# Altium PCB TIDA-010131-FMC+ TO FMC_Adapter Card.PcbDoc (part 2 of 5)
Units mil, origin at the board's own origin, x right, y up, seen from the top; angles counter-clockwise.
Board outline 2874.02 x 2362.2 mil, 12 copper layers (L1_Top Layer, L2_GND, L3_GND, L4_Signal layer1, L5_GND, L6_Signal Layer2, L7_GND, L8_Signal Layer3, L9_GND, L10_Signal Layer4, L11_GND, L12_Bottom Layer), stack 65.6 mil thick; 64 components, 219 nets, 2252 pads, 791 vias.
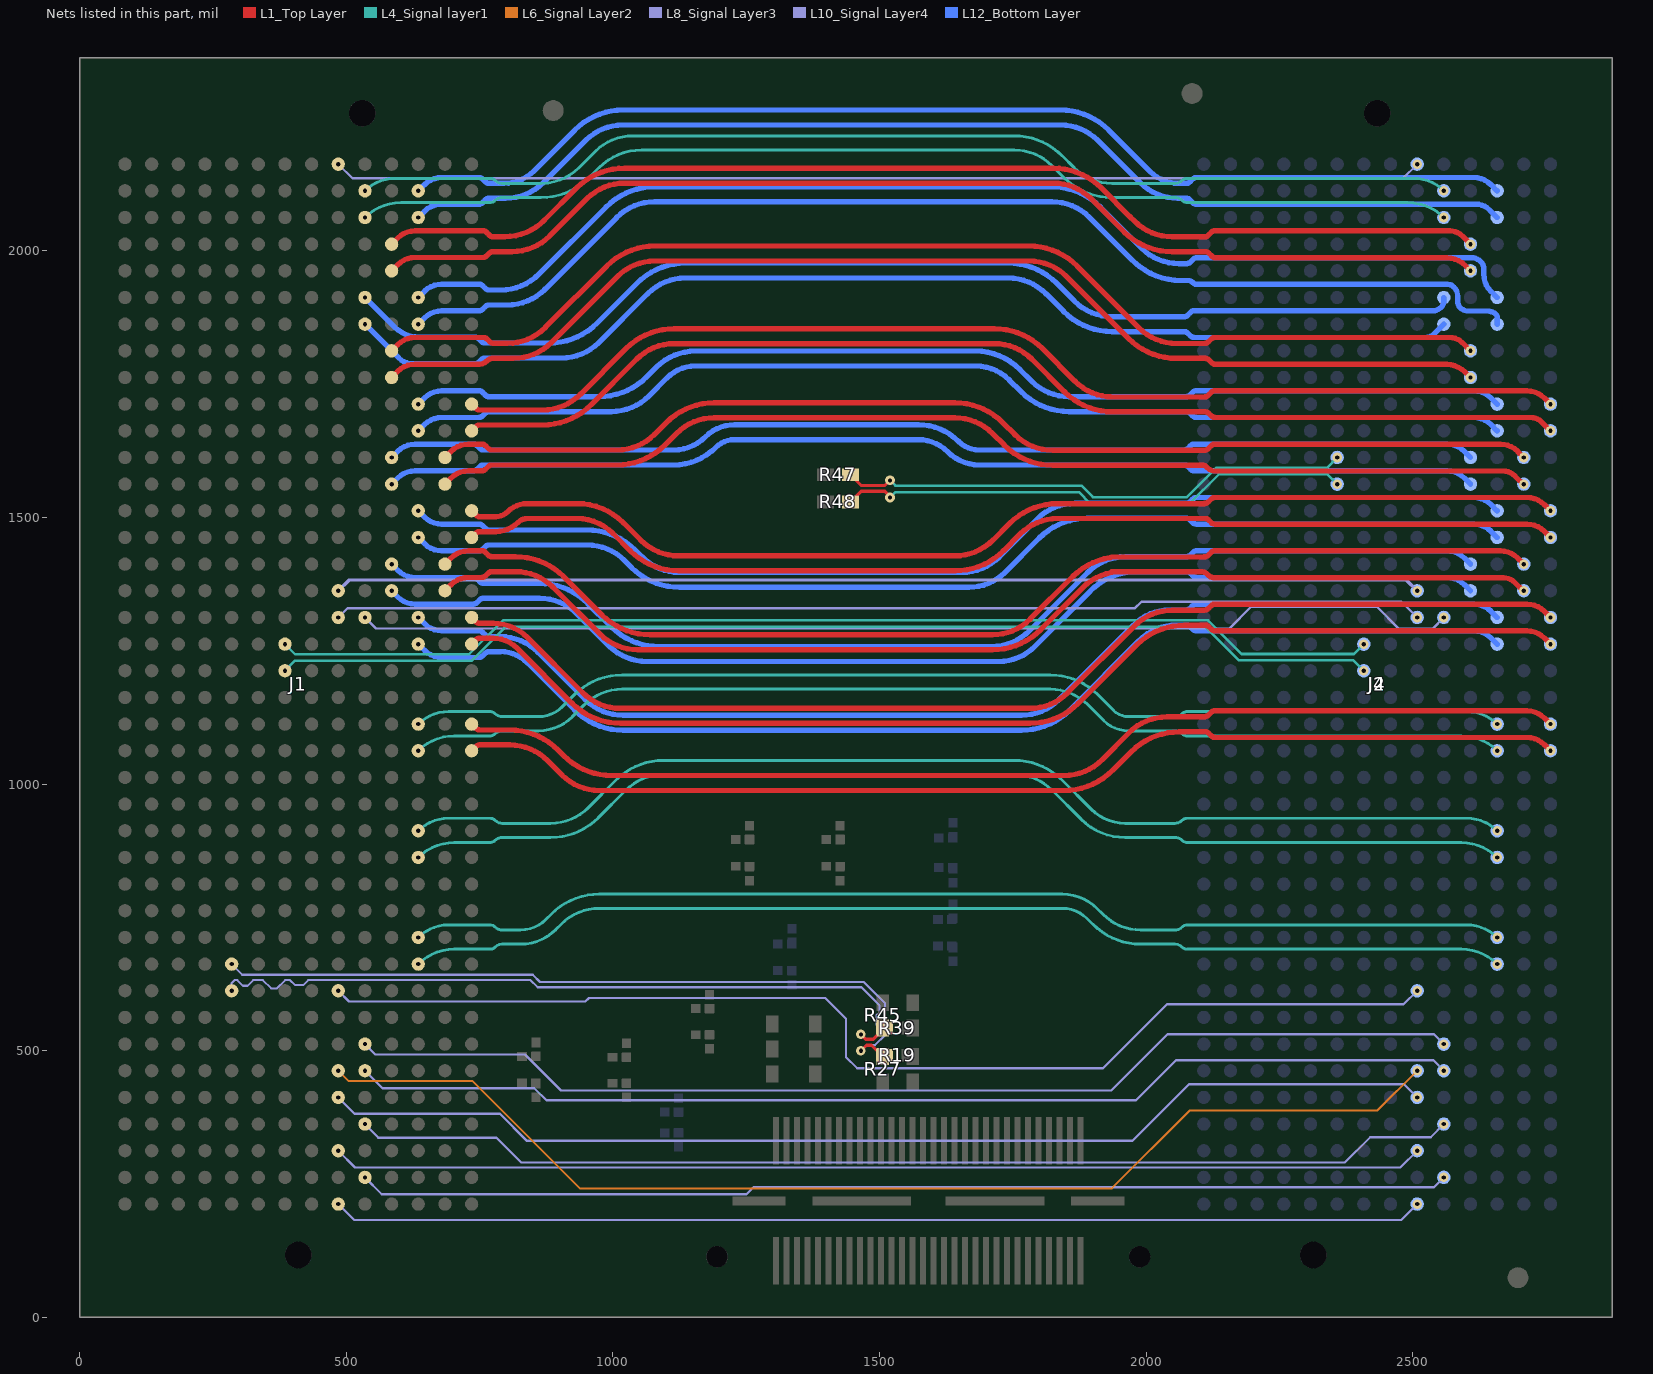
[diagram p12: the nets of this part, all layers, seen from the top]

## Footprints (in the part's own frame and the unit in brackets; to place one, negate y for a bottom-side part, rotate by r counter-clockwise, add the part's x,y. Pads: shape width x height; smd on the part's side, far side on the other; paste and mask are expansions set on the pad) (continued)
Samtec_ASP-184329-01 [mil] "Socket, 50 mil, 40x14, Gold, SMT"
  round 25 smd paste-25.2: A1(-975,225) A2(-925,225) A3(-875,225) A4(-825,225) A5(-775,225) A6(-725,225) A7(-675,225) A8(-625,225) A9(-575,225) A10(-525,225) A11(-475,225) A12(-425,225) A13(-375,225) A14(-325,225) A15(-275,225) A16(-225,225) A17(-175,225) A18(-125,225) A19(-75,225) A20(-25,225) A21(25,225) A22(75,225) A23(125,225) A24(175,225) A25(225,225) A26(275,225) A27(325,225) A28(375,225) A29(425,225) A30(475,225) A31(525,225) A32(575,225) A33(625,225) A34(675,225) A35(725,225) A36(775,225) A37(825,225) A38(875,225) A39(925,225) A40(975,225) B1(-975,175) B2(-925,175) B3(-875,175) B4(-825,175) B5(-775,175) B6(-725,175) B7(-675,175) B8(-625,175) B9(-575,175) B10(-525,175) B11(-475,175) B12(-425,175) B13(-375,175) B14(-325,175) B15(-275,175) B16(-225,175) B17(-175,175) B18(-125,175) B19(-75,175) B20(-25,175) B21(25,175) B22(75,175) B23(125,175) B24(175,175) B25(225,175) B26(275,175) B27(325,175) B28(375,175) B29(425,175) B30(475,175) B31(525,175) B32(575,175) B33(625,175) B34(675,175) B35(725,175) B36(775,175) B37(825,175) B38(875,175) B39(925,175) B40(975,175) C1(-975,125) C2(-925,125) C3(-875,125) C4(-825,125) C5(-775,125) C6(-725,125) C7(-675,125) C8(-625,125) C9(-575,125) C10(-525,125) C11(-475,125) C12(-425,125) C13(-375,125) C14(-325,125) C15(-275,125) C16(-225,125) C17(-175,125) C18(-125,125) C19(-75,125) C20(-25,125) C21(25,125) C22(75,125) C23(125,125) C24(175,125) C25(225,125) C26(275,125) C27(325,125) C28(375,125) C29(425,125) C30(475,125) C31(525,125) C32(575,125) C33(625,125) C34(675,125) C35(725,125) C36(775,125) C37(825,125) C38(875,125) C39(925,125) C40(975,125) D1(-975,75) D2(-925,75) D3(-875,75) D4(-825,75) D5(-775,75) D6(-725,75) D7(-675,75) D8(-625,75) D9(-575,75) D10(-525,75) D11(-475,75) D12(-425,75) D13(-375,75) D14(-325,75) D15(-275,75) D16(-225,75) D17(-175,75) D18(-125,75) D19(-75,75) D20(-25,75) D21(25,75) D22(75,75) D23(125,75) D24(175,75) D25(225,75) D26(275,75) D27(325,75) D28(375,75) D29(425,75) D30(475,75) D31(525,75) D32(575,75) D33(625,75) D34(675,75) D35(725,75) D36(775,75) D37(825,75) D38(875,75) D39(925,75) D40(975,75) E1(-975,25) E2(-925,25) E3(-875,25) E4(-825,25) E5(-775,25) E6(-725,25) E7(-675,25) E8(-625,25) E9(-575,25) E10(-525,25) E11(-475,25) E12(-425,25) E13(-375,25) E14(-325,25) E15(-275,25) E16(-225,25) E17(-175,25) E18(-125,25) E19(-75,25) E20(-25,25) E21(25,25) E22(75,25) E23(125,25) E24(175,25) E25(225,25) E26(275,25) E27(325,25) E28(375,25) E29(425,25) E30(475,25) E31(525,25) E32(575,25) E33(625,25) E34(675,25) E35(725,25) E36(775,25) E37(825,25) E38(875,25) E39(925,25) E40(975,25) F1(-975,-25) F2(-925,-25) F3(-875,-25) F4(-825,-25) F5(-775,-25) F6(-725,-25) F7(-675,-25) F8(-625,-25) F9(-575,-25) F10(-525,-25) F11(-475,-25) F12(-425,-25) F13(-375,-25) F14(-325,-25) F15(-275,-25) F16(-225,-25) F17(-175,-25) F18(-125,-25) F19(-75,-25) F20(-25,-25) F21(25,-25) F22(75,-25) F23(125,-25) F24(175,-25) F25(225,-25) F26(275,-25) F27(325,-25) F28(375,-25) F29(425,-25) F30(475,-25) F31(525,-25) F32(575,-25) F33(625,-25) F34(675,-25) F35(725,-25) F36(775,-25) F37(825,-25) F38(875,-25) F39(925,-25) F40(975,-25) G1(-975,-75) G2(-925,-75) G3(-875,-75) G4(-825,-75) G5(-775,-75) G6(-725,-75) G7(-675,-75) G8(-625,-75) G9(-575,-75) G10(-525,-75) G11(-475,-75) G12(-425,-75) G13(-375,-75) G14(-325,-75) G15(-275,-75) G16(-225,-75) G17(-175,-75) G18(-125,-75) G19(-75,-75) G20(-25,-75) G21(25,-75) G22(75,-75) G23(125,-75) G24(175,-75) G25(225,-75) G26(275,-75) G27(325,-75) G28(375,-75) G29(425,-75) G30(475,-75) G31(525,-75) G32(575,-75) G33(625,-75) G34(675,-75) G35(725,-75) G36(775,-75) G37(825,-75) G38(875,-75) G39(925,-75) G40(975,-75) H1(-975,-125) H2(-925,-125) H3(-875,-125) H4(-825,-125) H5(-775,-125) H6(-725,-125) H7(-675,-125) H8(-625,-125) H9(-575,-125) H10(-525,-125) H11(-475,-125) H12(-425,-125) H13(-375,-125) H14(-325,-125) H15(-275,-125) H16(-225,-125) H17(-175,-125) H18(-125,-125) H19(-75,-125) H20(-25,-125) H21(25,-125) H22(75,-125) H23(125,-125) H24(175,-125) H25(225,-125) H26(275,-125) H27(325,-125) H28(375,-125) H29(425,-125) H30(475,-125) H31(525,-125) H32(575,-125) H33(625,-125) H34(675,-125) H35(725,-125) H36(775,-125) H37(825,-125) H38(875,-125) H39(925,-125) H40(975,-125) J1(-975,-175) J2(-925,-175) J3(-875,-175) J4(-825,-175) J5(-775,-175) J6(-725,-175) J7(-675,-175) J8(-625,-175) J9(-575,-175) J10(-525,-175) J11(-475,-175) J12(-425,-175) J13(-375,-175) J14(-325,-175) J15(-275,-175) J16(-225,-175) J17(-175,-175) J18(-125,-175) J19(-75,-175) J20(-25,-175) J21(25,-175) J22(75,-175) J23(125,-175) J24(175,-175) J25(225,-175) J26(275,-175) J27(325,-175) J28(375,-175) J29(425,-175) J30(475,-175) J31(525,-175) J32(575,-175) J33(625,-175) J34(675,-175) J35(725,-175) J36(775,-175) J37(825,-175) J38(875,-175) J39(925,-175) J40(975,-175) K1(-975,-225) K2(-925,-225) K3(-875,-225) K4(-825,-225) K5(-775,-225) K6(-725,-225) K7(-675,-225) K8(-625,-225) K9(-575,-225) K10(-525,-225) K11(-475,-225) K12(-425,-225) K13(-375,-225) K14(-325,-225) K15(-275,-225) K16(-225,-225) K17(-175,-225) K18(-125,-225) K19(-75,-225) K20(-25,-225) K21(25,-225) K22(75,-225) K23(125,-225) K24(175,-225) K25(225,-225) K26(275,-225) K27(325,-225) K28(375,-225) K29(425,-225) K30(475,-225) K31(525,-225) K32(575,-225) K33(625,-225) K34(675,-225) K35(725,-225) K36(775,-225) K37(825,-225) K38(875,-225) K39(925,-225) K40(975,-225) L1(-975,-275) L2(-925,-275) L3(-875,-275) L4(-825,-275) L5(-775,-275) L6(-725,-275) L7(-675,-275) L8(-625,-275) L9(-575,-275) L10(-525,-275) L11(-475,-275) L12(-425,-275) L13(-375,-275) L14(-325,-275) L15(-275,-275) L16(-225,-275) L17(-175,-275) L18(-125,-275) L19(-75,-275) L20(-25,-275) L21(25,-275) L22(75,-275) L23(125,-275) L24(175,-275) L25(225,-275) L26(275,-275) L27(325,-275) L28(375,-275) L29(425,-275) L30(475,-275) L31(525,-275) L32(575,-275) L33(625,-275) L34(675,-275) L35(725,-275) L36(775,-275) L37(825,-275) L38(875,-275) L39(925,-275) L40(975,-275) M1(-975,-325) M2(-925,-325) M3(-875,-325) M4(-825,-325) M5(-775,-325) M6(-725,-325) M7(-675,-325) M8(-625,-325) M9(-575,-325) M10(-525,-325) M11(-475,-325) M12(-425,-325) M13(-375,-325) M14(-325,-325) M15(-275,-325) M16(-225,-325) M17(-175,-325) M18(-125,-325) M19(-75,-325) M20(-25,-325) M21(25,-325) M22(75,-325) M23(125,-325) M24(175,-325) M25(225,-325) M26(275,-325) M27(325,-325) M28(375,-325) M29(425,-325) M30(475,-325) M31(525,-325) M32(575,-325) M33(625,-325) M34(675,-325) M35(725,-325) M36(775,-325) M37(825,-325) M38(875,-325) M39(925,-325) M40(975,-325) Y1(-975,325) Y2(-925,325) Y3(-875,325) Y4(-825,325) Y5(-775,325) Y6(-725,325) Y7(-675,325) Y8(-625,325) Y9(-575,325) Y10(-525,325) Y11(-475,325) Y12(-425,325) Y13(-375,325) Y14(-325,325) Y15(-275,325) Y16(-225,325) Y17(-175,325) Y18(-125,325) Y19(-75,325) Y20(-25,325) Y21(25,325) Y22(75,325) Y23(125,325) Y24(175,325) Y25(225,325) Y26(275,325) Y27(325,325) Y28(375,325) Y29(425,325) Y30(475,325) Y31(525,325) Y32(575,325) Y33(625,325) Y34(675,325) Y35(725,325) Y36(775,325) Y37(825,325) Y38(875,325) Y39(925,325) Y40(975,325) Z1(-975,275) Z2(-925,275) Z3(-875,275) Z4(-825,275) Z5(-775,275) Z6(-725,275) Z7(-675,275) Z8(-625,275) Z9(-575,275) Z10(-525,275) Z11(-475,275) Z12(-425,275) Z13(-375,275) Z14(-325,275) Z15(-275,275) Z16(-225,275) Z17(-175,275) Z18(-125,275) Z19(-75,275) Z20(-25,275) Z21(25,275) Z22(75,275) Z23(125,275) Z24(175,275) Z25(225,275) Z26(275,275) Z27(325,275) Z28(375,275) Z29(425,275) Z30(475,275) Z31(525,275) Z32(575,275) Z33(625,275) Z34(675,275) Z35(725,275) Z36(775,275) Z37(825,275) Z38(875,275) Z39(925,275) Z40(975,275)
  round 50 hole 50 unplated mask+5: ""(-1070.5,120) ""(1070.5,0)
  round 35 on Top Paste: ""(-975,325) ""(-975,-275) ""(-975,-225) ""(-975,-175) ""(-975,-125) ""(-975,-75) ""(-975,-25) ""(-975,25) ""(-975,75) ""(-975,125) ""(-975,175) ""(-975,225) ""(-975,275) ""(-975,-325) ""(-925,325) ""(-925,-175) ""(-925,-75) ""(-925,75) ""(-925,175) ""(-925,-275) ""(-925,-225) ""(-925,-125) ""(-925,-25) ""(-925,25) ""(-925,125) ""(-925,225) ""(-925,275) ""(-925,-325) ""(-875,325) ""(-875,-275) ""(-875,-225) ""(-875,-175) ""(-875,-125) ""(-875,-75) ""(-875,-25) ""(-875,25) ""(-875,75) ""(-875,125) ""(-875,175) ""(-875,225) ""(-875,275) ""(-875,-325) ""(-825,325) ""(-825,-275) ""(-825,-175) ""(-825,-125) ""(-825,-75) ""(-825,-25) ""(-825,25) ""(-825,75) ""(-825,125) ""(-825,175) ""(-825,225) ""(-825,275) ""(-825,-325) ""(-825,-225) ""(-775,325) ""(-775,-275) ""(-775,-225) ""(-775,-125) ""(-775,-75) ""(-775,-25) ""(-775,25) ""(-775,125) ""(-775,175) ""(-775,225) ""(-775,275) ""(-775,-325) ""(-775,-175) ""(-775,75) ""(-725,-275) ""(-725,275) ""(-725,325) ""(-725,-225) ""(-725,-175) ""(-725,-125) ""(-725,-75) ""(-725,-25) ""(-725,25) ""(-725,75) ""(-725,125) ""(-725,175) ""(-725,225) ""(-725,-325) ""(-675,325) ""(-675,-275) ""(-675,-225) ""(-675,-175) ""(-675,-125) ""(-675,-75) ""(-675,-25) ""(-675,25) ""(-675,75) ""(-675,125) ""(-675,175) ""(-675,225) ""(-675,275) ""(-675,-325) ""(-625,325) ""(-625,-225) ""(-625,-175) ""(-625,-125) ""(-625,-75) ""(-625,25) ""(-625,75) ""(-625,125) ""(-625,175) ""(-625,275) ""(-625,-325) ""(-625,-275) ""(-625,-25) ""(-625,225) ""(-575,325) ""(-575,-275) ""(-575,-175) ""(-575,-75) ""(-575,-25) ""(-575,75) ""(-575,125) ""(-575,175) ""(-575,225) ""(-575,-325) ""(-575,-225) ""(-575,-125) ""(-575,25) ""(-575,275) ""(-525,325) ""(-525,-275) ""(-525,-225) ""(-525,-125) ""(-525,-75) ""(-525,-25) ""(-525,25) ""(-525,75) ""(-525,125) ""(-525,175) ""(-525,225) ""(-525,275) ""(-525,-325) ""(-525,-175) ""(-475,275) ""(-475,-25) ""(-475,25) ""(-475,-275) ""(-475,175) ""(-475,225) ""(-475,325) ""(-475,-125) ""(-475,-75) ""(-475,75) ""(-475,125) ""(-475,-325) ""(-475,-225) ""(-475,-175) ""(-425,175) ""(-425,225) ""(-425,275) ""(-425,325) ""(-425,-125) ""(-425,-75) ""(-425,-25) ""(-425,25) ""(-425,75) ""(-425,125) ""(-425,-325) ""(-425,-275) ""(-425,-225) ""(-425,-175) ""(-375,175) ""(-375,275) ""(-375,325) ""(-375,-125) ""(-375,-75) ""(-375,25) ""(-375,75) ""(-375,125) ""(-375,-325) ""(-375,-275) ""(-375,-225) ""(-375,-175) ""(-375,225) ""(-375,-25) ""(-325,175) ""(-325,225) ""(-325,325) ""(-325,-125) ""(-325,-75) ""(-325,-25) ""(-325,75) ""(-325,125) ""(-325,-325) ""(-325,-275) ""(-325,-225) ""(-325,-175) ""(-325,275) ""(-325,25) ""(-275,-175) ""(-275,175) ""(-275,225) ""(-275,275) ""(-275,325) ""(-275,-125) ""(-275,-75) ""(-275,-25) ""(-275,25) ""(-275,75) ""(-275,125) ""(-275,-325) ""(-275,-275) ""(-275,-225) ""(-225,275) ""(-225,225) ""(-225,-25) ""(-225,25) ""(-225,-225) ""(-225,-125) ""(-225,-275) ""(-225,325) ""(-225,125) ""(-225,175) ""(-225,-75) ""(-225,75) ""(-225,-175) ""(-225,-325) ""(-175,275) ""(-175,325) ""(-175,125) ""(-175,225) ""(-175,-75) ""(-175,-25) ""(-175,75) ""(-175,-175) ""(-175,-125) ""(-175,-325) ""(-175,-275) ""(-175,175) ""(-175,25) ""(-175,-225) ""(-125,275) ""(-125,125) ""(-125,175) ""(-125,-25) ""(-125,25) ""(-125,-75) ""(-125,-125) ""(-125,-225) ""(-125,-325) ""(-125,-275) ""(-125,325) ""(-125,225) ""(-125,75) ""(-125,-175) ""(-75,325) ""(-75,225) ""(-75,125) ""(-75,175) ""(-75,75) ""(-75,-25) ""(-75,25) ""(-75,-75) ""(-75,-175) ""(-75,-125) ""(-75,-225) ""(-75,-325) ""(-75,-275) ""(-75,275) ""(-25,175) ""(-25,75) ""(-25,-175) ""(-25,325) ""(-25,275) ""(-25,225) ""(-25,125) ""(-25,25) ""(-25,-25) ""(-25,-75) ""(-25,-125) ""(-25,-225) ""(-25,-275) ""(-25,-325) ""(25,325) ""(25,275) ""(25,225) ""(25,175) ""(25,125) ""(25,75) ""(25,25) ""(25,-25) ""(25,-75) ""(25,-125) ""(25,-175) ""(25,-225) ""(25,-275) ""(25,-325) ""(75,275) ""(75,325) ""(75,225) ""(75,125) ""(75,175) ""(75,75) ""(75,-25) ""(75,25) ""(75,-75) ""(75,-175) ""(75,-125) ""(75,-325) ""(75,-275) ""(75,-225) ""(125,275) ""(125,325) ""(125,225) ""(125,125) ""(125,175) ""(125,-25) ""(125,25) ""(125,-75) ""(125,-125) ""(125,-225) ""(125,-325) ""(125,-275) ""(125,75) ""(125,-175) ""(175,275) ""(175,325) ""(175,125) ""(175,175) ""(175,225) ""(175,-75) ""(175,-25) ""(175,25) ""(175,75) ""(175,-225) ""(175,-175) ""(175,-125) ""(175,-325) ""(175,-275) ""(225,325) ""(225,175) ""(225,-75) ""(225,75) ""(225,-175) ""(225,275) ""(225,125) ""(225,225) ""(225,-25) ""(225,25) ""(225,-225) ""(225,-125) ""(225,-325) ""(225,-275) ""(275,175) ""(275,225) ""(275,275) ""(275,325) ""(275,-125) ""(275,-75) ""(275,-25) ""(275,25) ""(275,75) ""(275,125) ""(275,-325) ""(275,-275) ""(275,-225) ""(275,-175) ""(325,175) ""(325,225) ""(325,275) ""(325,325) ""(325,-125) ""(325,-75) ""(325,-25) ""(325,25) ""(325,75) ""(325,125) ""(325,-325) ""(325,-275) ""(325,-225) ""(325,-175) ""(375,175) ""(375,225) ""(375,275) ""(375,325) ""(375,-125) ""(375,-75) ""(375,-25) ""(375,25) ""(375,75) ""(375,125) ""(375,-325) ""(375,-275) ""(375,-225) ""(375,-175) ""(425,275) ""(425,-275) ""(425,175) ""(425,225) ""(425,325) ""(425,-125) ""(425,-75) ""(425,-25) ""(425,25) ""(425,75) ""(425,125) ""(425,-325) ""(425,-225) ""(425,-175) ""(475,175) ""(475,225) ""(475,275) ""(475,325) ""(475,-125) ""(475,-75) ""(475,-25) ""(475,25) ""(475,75) ""(475,125) ""(475,-325) ""(475,-275) ""(475,-225) ""(475,-175) ""(525,325) ""(525,-275) ""(525,-225) ""(525,-175) ""(525,-125) ""(525,-75) ""(525,25) ""(525,75) ""(525,125) ""(525,175) ""(525,275) ""(525,-325) ""(525,-25) ""(525,225) ""(575,325) ""(575,-275) ""(575,-225) ""(575,-175) ""(575,-125) ""(575,-75) ""(575,-25) ""(575,75) ""(575,125) ""(575,175) ""(575,225) ""(575,-325) ""(575,25) ""(575,275) ""(625,-175) ""(625,325) ""(625,-275) ""(625,-225) ""(625,-125) ""(625,-75) ""(625,-25) ""(625,25) ""(625,75) ""(625,125) ""(625,175) ""(625,225) ""(625,275) ""(625,-325) ""(675,-275) ""(675,-125) ""(675,-25) ""(675,25) ""(675,275) ""(675,325) ""(675,-225) ""(675,-175) ""(675,-75) ""(675,75) ""(675,125) ""(675,175) ""(675,225) ""(675,-325) ""(725,325) ""(725,-275) ""(725,-225) ""(725,-175) ""(725,-125) ""(725,-75) ""(725,-25) ""(725,25) ""(725,75) ""(725,125) ""(725,175) ""(725,225) ""(725,275) ""(725,-325) ""(775,325) ""(775,-275) ""(775,-225) ""(775,-175) ""(775,-125) ""(775,-75) ""(775,-25) ""(775,25) ""(775,75) ""(775,125) ""(775,175) ""(775,275) ""(775,-325) ""(775,225) ""(825,325) ""(825,-275) ""(825,-225) ""(825,-175) ""(825,-125) ""(825,-75) ""(825,-25) ""(825,25) ""(825,75) ""(825,125) ""(825,175) ""(825,225) ""(825,-325) ""(825,275) ""(875,-175) ""(875,75) ""(875,175) ""(875,325) ""(875,-275) ""(875,-225) ""(875,-125) ""(875,-75) ""(875,-25) ""(875,25) ""(875,125) ""(875,225) ""(875,275) ""(875,-325) ""(925,325) ""(925,-275) ""(925,-225) ""(925,-175) ""(925,-125) ""(925,-75) ""(925,-25) ""(925,25) ""(925,75) ""(925,125) ""(925,175) ""(925,225) ""(925,275) ""(925,-325) ""(975,325) ""(975,-275) ""(975,-175) ""(975,-125) ""(975,-75) ""(975,-25) ""(975,75) ""(975,125) ""(975,175) ""(975,225) ""(975,275) ""(975,-325) ""(975,-225) ""(975,25)
  silkscreen extent -1128,-362 1135,374, body extent -1131,-362 1131,362, height 267
Samtec_QSH-030-01-X-D-A [mm] "Receptacle, 0.5 mm, 30x2, TH"
  rect 2.27x0.279 smd: 1(-2.865,7.25) 2(2.865,7.25) 3(-2.865,6.75) 4(2.865,6.75) 5(-2.865,6.25) 6(2.865,6.25) 7(-2.865,5.75) 8(2.865,5.75) 9(-2.865,5.25) 10(2.865,5.25) 11(-2.865,4.75) 12(2.865,4.75) 13(-2.865,4.25) 14(2.865,4.25) 15(-2.865,3.75) 16(2.865,3.75) 17(-2.865,3.25) 18(2.865,3.25) 19(-2.865,2.75) 20(2.865,2.75) 21(-2.865,2.25) 22(2.865,2.25) 23(-2.865,1.75) 24(2.865,1.75) 25(-2.865,1.25) 26(2.865,1.25) 27(-2.865,0.75) 28(2.865,0.75) 29(-2.865,0.25) 30(2.865,0.25) 31(-2.865,-0.25) 32(2.865,-0.25) 33(-2.865,-0.75) 34(2.865,-0.75) 35(-2.865,-1.25) 36(2.865,-1.25) 37(-2.865,-1.75) 38(2.865,-1.75) 39(-2.865,-2.25) 40(2.865,-2.25) 41(-2.865,-2.75) 42(2.865,-2.75) 43(-2.865,-3.25) 44(2.865,-3.25) 45(-2.865,-3.75) 46(2.865,-3.75) 47(-2.865,-4.25) 48(2.865,-4.25) 49(-2.865,-4.75) 50(2.865,-4.75) 51(-2.865,-5.25) 52(2.865,-5.25) 53(-2.865,-5.75) 54(2.865,-5.75) 55(-2.865,-6.25) 56(2.865,-6.25) 57(-2.865,-6.75) 58(2.865,-6.75) 59(-2.865,-7.25) 60(2.865,-7.25)
  round 1.02 hole 1.02 unplated mask+0.127: MH1(2.67,10.065) MH2(2.67,-10.065)
  rect 0.43x2.54 smd: MP1(0,8.065) MP4(0,-8.065)
  rect 0.43x4.7 smd: MP2(0,3.175) MP3(0,-3.175)
  silkscreen extent -3.9,-10.66 3.62,10.66, body extent -3.75,-10.64 3.75,10.67, height 3.25
WEEE_Minimum [mil] "WEEElie bin"
  silkscreen extent -95,-172 99,104

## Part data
FID1 FID2 FID3: "Fiducial mark.  There is nothing to buy or mount.", Manufacturer=N/A
J1: "Socket, 50 mil, 40x14, Gold, SMT", Color=Black, Manufacturer=Samtec, Supplier Part Number 1=SAM9172-ND
J2: "Connector, 1.27mm, 40x10, Black, SMT", Color=Black, Manufacturer=Samtec, Supplier Part Number 1=2433503
J3: "Receptacle, 0.5 mm, 30x2, Gold, TH", Color=Black, Manufacturer=Samtec, Supplier Part Number 1=SAM8180-ND
J4: "14 ROW .050 PITCH TERMINAL ARRAY ASM.", Manufacturer=SAMTEC
LBL1: library part THT-14-423-10, "Thermal Transfer Printable Labels, 0.650\" W x 0.200\" H - 10,000 per roll", Alternate Manufacturer=-, Manufacturer=Brady, Supplier Part Number 1=2065596
Logo1: library part ESD_Susceptible, "ESD Susceptible Symbol"
Logo2: library part Pb-Free
Logo3: library part FCC_disclaimer, "FCC_disclaimer"
Logo4: library part CMP-0074769-1
R1 R2 R3 R4 R5 R6 R9 R10 R11 R12 R13 R14 R15 R16 R17 R18 R20 R21 R22 R23 R24 R26 R28 R29 R30 R31 R32 R33 R34 R35 R36 R37 R41 R42 R43 R44: "RES, 0, 5%, 0.05 W, AEC-Q200 Grade 0, 0201", Manufacturer=Panasonic, Power_W=0.05, Supplier Part Number 1=P15979CT-ND, TempCo=ppm/C, Tolerance_%=5, Value1=5%, Value2=0.05W, Value_Code=0000, ValueDisplayed=0
R7 R8 R19 R25 R27 R38 R39 R40 R45 R46 R47 R48: "RES, 0, 5%, 0.063 W, 0402", Manufacturer=Vishay-Dale, Power_W=0.063, Supplier Part Number 1=541-0.0JCT-ND, TempCo="200 ppm/C", Tolerance_%=5, Value1=5%, Value2=0.063W, Value_Code=0000, ValueDisplayed=0
ZZ1: library part AssemblyNoteLabel, Alternate Manufacturer=-
ZZ2 ZZ3 ZZ4: library part AssemblyNote, Alternate Manufacturer=-

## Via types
v1: diameter 18, hole 8, L1_Top Layer to L12_Bottom Layer, 791 vias

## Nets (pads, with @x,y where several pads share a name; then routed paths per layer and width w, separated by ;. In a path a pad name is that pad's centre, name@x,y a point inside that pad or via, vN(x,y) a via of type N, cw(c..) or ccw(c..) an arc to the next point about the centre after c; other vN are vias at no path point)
ADC_ALT_SYNC_N: J1.H32 R39.1 R45.2 | length 1439.1
  L1_Top Layer w6: v1(1465,530.62) 1474.19,521.43 1488.19,521.43 R39.1@1509.38,542.62
  L8_Signal Layer3 w4: v1(285,612.5) 285,627 290.5,632.5 295.5,632.5 306,622 315,622 325.5,632.5 343.5,632.5 359,617 370,617 385.5,632.5 394.5,632.5 404,623 419,623 428.5,632.5 845.5,632.5 859,619 1466,619 1500,585 1500,572 1494,566 1494,549 1500,543 1500,533.32 1487,520.32 1475.3,520.32 v1(1465,530.62)
ADC_ALT_SYNC_P: J1.H31 R19.1 R27.1 | length 1426.5
  L1_Top Layer w6: v1(1465,500.02) 1475.41,510.43 1484.81,510.43 R27.1@1506,489.24
  L8_Signal Layer3 w4: v1(285,662.5) 305,642.5 849.64,642.5 863.14,629 1470.14,629 1510,589.14 1510,529.18 1491.14,510.32 1475.3,510.32 v1(1465,500.02)
ADC_DA0_N: J1.C7 J2.C7 J4.C7 | length 2154.5
  L12_Bottom Layer w10: v1(535,1862.5) 598.54,1798.96 ccw(c625,1825.42) 625,1788 741,1788 ccw(c741,1797.99) 748.07,1790.93 753.21,1796.07 cw(c760.28,1789.01) 760.28,1799 903.18,1799 ccw(c903.18,1899) 973.89,1828.29 1065.31,1919.71 cw(c1136.02,1849) 1136.02,1949 1740.98,1949 cw(c1740.98,1849) 1811.69,1919.71 1845.41,1885.99 ccw(c1935.92,1976.5) 1935.92,1848.5 2070.72,1848.5 cw(c2070.72,1838.51) 2077.79,1845.57 2082.93,1840.43 ccw(c2090,1847.49) 2090,1837.5 2524.64,1837.5 ccw(c2524.64,1857.67) 2538.91,1843.41 J2.C7@2558,1862.5
ADC_DA0_P: J1.C6 J2.C6 J4.C6 | length 2154.9
  L12_Bottom Layer w10: v1(535,1912.5) 590.05,1857.45 ccw(c637,1904.39) 637,1838 741,1838 cw(c741,1828.01) 748.07,1835.07 753.21,1829.93 ccw(c760.28,1836.99) 760.28,1827 879.98,1827 ccw(c879.98,1955) 970.49,1864.49 1045.51,1939.51 cw(c1136.02,1849) 1136.02,1977 1695.58,1977 ; 1698.6,1977 1740.98,1977 cw(c1740.98,1849) 1831.49,1939.51 1865.21,1905.79 ccw(c1935.92,1976.5) 1935.92,1876.5 2070.72,1876.5 ccw(c2070.72,1886.49) 2077.79,1879.43 2082.93,1884.57 cw(c2090,1877.51) 2090,1887.5 2537.31,1887.5 ccw(c2537.31,1909.69) 2553,1894 ccw(c2540.93,1906.07) 2558,1906.07 J2.C6@2558,1912.5
ADC_DA1_N: J1.A3 J2.A3 J4.A3 | length 2144.2
  L12_Bottom Layer w10: v1(635,2062.5) 646.53,2074.03 cw(c679.05,2041.51) 679.05,2087.5 748.5,2087.5 ccw(c748.5,2097.49) 755.57,2090.43 760.71,2095.57 cw(c767.78,2088.51) 767.78,2098.5 798.68,2098.5 ccw(c798.68,2198.5) 869.39,2127.79 948.31,2206.71 cw(c1019.02,2136) 1019.02,2236 1838.98,2236 cw(c1838.98,2136) 1909.69,2206.71 1988.61,2127.79 ccw(c2059.32,2198.5) 2059.32,2098.5 2074.91,2098.5 cw(c2074.91,2088.51) 2081.98,2095.57 2087.12,2090.43 ccw(c2094.19,2097.49) 2094.19,2087.5 2617.37,2087.5 cw(c2617.37,2049.77) 2644.05,2076.45 ; 2644.05,2076.45 J2.A3@2658,2062.5
ADC_DA1_P: J1.A2 J2.A2 J4.A2 | length 2143.3
  L12_Bottom Layer w10: v1(635,2112.5) 646.53,2124.03 cw(c679.05,2091.51) 679.05,2137.5 748.5,2137.5 cw(c748.5,2127.51) 755.57,2134.57 760.71,2129.43 ccw(c767.78,2136.49) 767.78,2126.5 795.27,2126.5 ccw(c795.27,2206.73) 852,2150 928.51,2226.51 cw(c1019.02,2136) 1019.02,2264 1838.98,2264 cw(c1838.98,2136) 1929.49,2226.51 2007.23,2148.77 ccw(c2061,2202.55) 2061,2126.5 2074.91,2126.5 ccw(c2074.91,2136.49) 2081.98,2129.43 2087.12,2134.57 cw(c2094.19,2127.51) 2094.19,2137.5 2613.95,2137.5 cw(c2613.95,2091.51) 2646.47,2124.03 J2.A2@2658,2112.5
ADC_DA2_N: J1.A7 J2.A7 J4.A7 | length 2211.5
  L12_Bottom Layer w10: v1(635,1862.5) 646.53,1874.03 cw(c679.05,1841.51) 679.05,1887.5 748.5,1887.5 ccw(c748.5,1897.49) 755.57,1890.43 760.71,1895.57 cw(c767.78,1888.51) 767.78,1898.5 801.68,1898.5 ccw(c801.68,1998.5) 872.39,1927.79 1007.31,2062.71 cw(c1078.02,1992) 1078.02,2092 1822.98,2092 cw(c1822.98,1992) 1893.69,2062.71 1974.57,1981.84 ccw(c2065.07,2072.35) 1988.2,1970 ccw(c2065.07,2072.35) 2030.28,1949.17 ccw(c2065.07,2072.35) 2065.07,1944.35 2080.51,1944.35 cw(c2075.52,1927.52) 2087.77,1940.09 cw(c2075.52,1927.52) 2087.93,1939.93 ccw(c2095,1946.99) 2095,1937 2564.93,1937 cw(c2564.93,1919.93) 2577,1932 cw(c2560.1,1915.1) 2584,1915.1 2584,1904.66 ccw(c2600.07,1904.66) 2588.71,1893.29 ccw(c2603.9,1908.49) 2603.9,1887 2640.31,1887 cw(c2640.31,1864.81) 2656,1880.5 cw(c2651.17,1875.67) 2658,1875.67 J2.A7@2658,1862.5
ADC_DA2_P: J1.A6 J2.A6 J4.A6 | length 2207.3
  L12_Bottom Layer w10: v1(635,1912.5) 646.53,1924.03 cw(c679.05,1891.51) 679.05,1937.5 748.5,1937.5 cw(c748.5,1927.51) 755.57,1934.57 760.71,1929.43 ccw(c767.78,1936.49) 767.78,1926.5 789.48,1926.5 ccw(c789.48,2027.94) 861.21,1956.21 987.51,2082.51 cw(c1078.02,1992) 1078.02,2120 1822.98,2120 cw(c1822.98,1992) 1913.49,2082.51 1990.71,2005.29 ccw(c2061.42,2076) 2061.42,1976 2075.72,1976 ccw(c2075.72,1985.99) 2082.79,1978.93 2087.93,1984.07 cw(c2095,1977.01) 2095,1987 2609.62,1987 cw(c2609.62,1961.93) 2627.34,1979.66 cw(c2613.69,1966) 2633,1966 2633,1956 ccw(c2677.66,1956) 2646.08,1924.42 J2.A6@2658,1912.5
ADC_DA3_N: J1.A11 J2.A11 J4.A11 | length 2101.1
  L12_Bottom Layer w10: v1(635,1662.5) 646.53,1674.03 cw(c679.05,1641.51) 679.05,1687.5 748.5,1687.5 ccw(c748.5,1697.49) 755.57,1690.43 760.71,1695.57 cw(c767.78,1688.51) 767.78,1698.5 996.68,1698.5 ccw(c996.68,1798.5) 1067.39,1727.79 1101.6,1762 cw(c1154.71,1708.89) 1154.71,1784 1680.23,1784 cw(c1680.23,1695.23) 1743,1758 1765.01,1735.99 ccw(c1855.52,1826.5) 1855.52,1698.5 2074.91,1698.5 cw(c2074.91,1688.51) 2081.98,1695.57 2087.12,1690.43 ccw(c2094.19,1697.49) 2094.19,1687.5 2613.95,1687.5 cw(c2613.95,1641.51) 2646.47,1674.03 J2.A11@2658,1662.5
ADC_DA3_P: J1.A10 J2.A10 J4.A10 | length 2098.7
  L12_Bottom Layer w10: v1(635,1712.5) 646.53,1724.03 cw(c679.05,1691.51) 679.05,1737.5 748.5,1737.5 cw(c748.5,1727.51) 755.57,1734.57 760.71,1729.43 ccw(c767.78,1736.49) 767.78,1726.5 973.48,1726.5 ccw(c973.48,1854.5) 1063.99,1763.99 1081.8,1781.8 cw(c1154.71,1708.89) 1154.71,1812 1680.23,1812 cw(c1680.23,1695.23) 1762.8,1777.8 1784.81,1755.79 ccw(c1855.52,1826.5) 1855.52,1726.5 2074.91,1726.5 ccw(c2074.91,1736.49) 2081.98,1729.43 2087.12,1734.57 cw(c2094.19,1727.51) 2094.19,1737.5 2613.95,1737.5 cw(c2613.95,1691.51) 2646.47,1724.03 J2.A10@2658,1712.5
ADC_DA4_N: J1.A15 J2.A15 J4.A15 | length 2113.4
  L12_Bottom Layer w10: v1(635,1462.5) 646.53,1450.97 ccw(c679.05,1483.49) 679.05,1437.5 748.5,1437.5 ccw(c748.5,1447.49) 755.57,1440.43 760.71,1445.57 cw(c767.78,1438.51) 767.78,1448.5 951.08,1448.5 cw(c951.08,1348.5) 1021.79,1419.21 1034.51,1406.49 ccw(c1125.02,1497) 1125.02,1369 1667.4,1369 ccw(c1667.4,1464.6) 1735,1397 1799.01,1461.01 cw(c1889.52,1370.5) 1889.52,1498.5 2074,1498.5 ; 2074.91,1498.5 cw(c2074.91,1488.51) 2081.98,1495.57 2087.12,1490.43 ccw(c2094.19,1497.49) 2094.19,1487.5 2613.95,1487.5 cw(c2613.95,1441.51) 2646.47,1474.03 J2.A15@2658,1462.5
ADC_DA4_P: J1.A14 J2.A14 J4.A14 | length 2114.4
  L12_Bottom Layer w10: v1(635,1512.5) 646.53,1500.97 ccw(c679.05,1533.49) 679.05,1487.5 748.5,1487.5 cw(c748.5,1477.51) 755.57,1484.57 760.71,1479.43 ccw(c767.78,1486.49) 767.78,1476.5 951.08,1476.5 cw(c951.08,1348.5) 1041.59,1439.01 1054.31,1426.29 ccw(c1125.02,1497) 1125.02,1397 1653.98,1397 ccw(c1653.98,1497) 1724.69,1426.29 1795.61,1497.21 cw(c1866.32,1426.5) 1866.32,1526.5 2074,1526.5 ; 2074.91,1526.5 ccw(c2074.91,1536.49) 2081.98,1529.43 2087.12,1534.57 cw(c2094.19,1527.51) 2094.19,1537.5 2613.95,1537.5 cw(c2613.95,1491.51) 2646.47,1524.03 J2.A14@2658,1512.5
ADC_DA5_N: J1.A19 J2.A19 J4.A19 | length 2171.7
  L12_Bottom Layer w10: v1(635,1262.5) 646.53,1250.97 ccw(c679.05,1283.49) 679.05,1237.5 748.5,1237.5 ccw(c748.5,1247.49) 755.57,1240.43 760.71,1245.57 cw(c767.78,1238.51) 767.78,1248.5 789,1248.5 cw(c789,1177.28) 839.36,1227.64 928.51,1138.49 ccw(c1019.02,1229) 928.57,1138.43 ccw(c1019.02,1229) 1019.02,1101 1765.58,1101 ccw(c1765.58,1229) 1856.03,1138.43 ccw(c1765.58,1229) 1856.09,1138.49 1986.81,1269.21 cw(c2057.52,1198.5) 2057.52,1298.5 2074.91,1298.5 cw(c2074.91,1288.51) 2081.98,1295.57 2087.12,1290.43 ccw(c2094.19,1297.49) 2094.19,1287.5 2613.95,1287.5 cw(c2613.95,1241.51) 2646.47,1274.03 J2.A19@2658,1262.5
ADC_DA5_P: J1.A18 J2.A18 J4.A18 | length 2173.1
  L12_Bottom Layer w10: v1(635,1312.5) 646.53,1300.97 ccw(c679.05,1333.49) 679.05,1287.5 748.5,1287.5 cw(c748.5,1277.51) 755.57,1284.57 760.71,1279.43 ccw(c767.78,1286.49) 767.78,1276.5 789,1276.5 cw(c789,1177.28) 859.16,1247.44 948.31,1158.29 ccw(c1019.02,1229) 1019.02,1129 1765.58,1129 ccw(c1765.58,1229) 1836.29,1158.29 1976.5,1298.5 cw(c2044.1,1230.9) 2044.1,1326.5 2074.91,1326.5 ccw(c2074.91,1336.49) 2081.98,1329.43 2087.12,1334.57 cw(c2094.19,1327.51) 2094.19,1337.5 2613.95,1337.5 cw(c2613.95,1291.51) 2646.47,1324.03 J2.A18@2658,1312.5
ADC_DA6_N: J1.B17 J2.B17 J4.B17 | length 2148
  L12_Bottom Layer w10: v1(585,1362.5) 596.53,1350.97 ccw(c629.05,1383.49) 629.05,1337.5 738,1337.5 ccw(c738,1347.49) 745.07,1340.43 750.21,1345.57 cw(c757.28,1338.51) 757.28,1348.5 862.08,1348.5 cw(c862.08,1248.5) 932.79,1319.21 992.71,1259.29 ccw(c1063.42,1330) 1017.07,1241.39 ccw(c1063.42,1330) 1063.42,1230 1723.4,1230 ccw(c1723.4,1325.6) 1791,1258 1895.09,1362.09 cw(c1983,1274.17) 1983,1398.5 2075.72,1398.5 cw(c2075.72,1388.51) 2082.79,1395.57 2087.93,1390.43 ccw(c2095,1397.49) 2095,1387.5 2563.95,1387.5 cw(c2563.95,1341.51) 2596.47,1374.03 J2.B17@2608,1362.5
ADC_DA6_P: J1.B16 J2.B16 J4.B16 | length 2146.4
  L12_Bottom Layer w10: v1(585,1412.5) 596.53,1400.97 ccw(c629.05,1433.49) 629.05,1387.5 738,1387.5 cw(c738,1377.51) 745.07,1384.57 750.21,1379.43 ccw(c757.28,1386.49) 757.28,1376.5 862.08,1376.5 cw(c862.08,1248.5) 952.59,1339.01 996.3,1295.3 ; 996.32,1295.28 ccw(c1086.35,1385.35) 1035.03,1268.8 ccw(c1086.35,1385.35) 1086.35,1258 1709.98,1258 ccw(c1709.98,1358) 1780.69,1287.29 1890.61,1397.21 cw(c1961.32,1326.5) 1961.32,1426.5 2075.72,1426.5 ccw(c2075.72,1436.49) 2082.79,1429.43 2087.93,1434.57 cw(c2095,1427.51) 2095,1437.5 2563.95,1437.5 cw(c2563.95,1391.51) 2596.47,1424.03 J2.B16@2608,1412.5
ADC_DA7_N: J1.B13 J2.B13 J4.B13 | length 2072.6
  L12_Bottom Layer w10: v1(585,1562.5) 596.53,1574.03 cw(c629.05,1541.51) 629.05,1587.5 738,1587.5 ccw(c738,1597.49) 745.07,1590.43 750.21,1595.57 cw(c757.28,1588.51) 757.28,1598.5 1113.85,1598.5 ccw(c1113.85,1710.15) 1192.8,1631.2 cw(c1228.53,1595.47) 1228.53,1646 1572.47,1646 cw(c1572.47,1567.47) 1628,1623 ccw(c1687.15,1682.15) 1687.15,1598.5 1802.4,1598.5 ; 1802.52,1598.5 2072,1598.5 cw(c2072,1591.6) 2076.88,1596.48 2082.93,1590.43 ccw(c2090,1597.49) 2090,1587.5 2563.95,1587.5 cw(c2563.95,1541.51) 2596.47,1574.03 J2.B13@2608,1562.5
ADC_DA7_P: J1.B12 J2.B12 J4.B12 | length 2073.8
  L12_Bottom Layer w10: v1(585,1612.5) 596.53,1624.03 cw(c629.05,1591.51) 629.05,1637.5 738,1637.5 cw(c738,1627.51) 745.07,1634.57 750.21,1629.43 ccw(c757.28,1636.49) 757.28,1626.5 1113.85,1626.5 ccw(c1113.85,1710.15) 1173,1651 cw(c1228.53,1595.47) 1228.53,1674 1572.47,1674 cw(c1572.47,1567.47) 1647.8,1642.8 ccw(c1687.15,1682.15) 1687.15,1626.5 2072,1626.5 ; 2070.72,1626.5 ccw(c2070.72,1636.49) 2077.79,1629.43 2082.93,1634.57 cw(c2090,1627.51) 2090,1637.5 2563.95,1637.5 cw(c2563.95,1591.51) 2596.47,1624.03 J2.B12@2608,1612.5
ADC_DB0_N: J1.B5 J2.B5 J4.B5 | length 2135
  L1_Top Layer w10: J1.B5@585,1962.5 596.53,1974.03 cw(c629.05,1941.51) 629.05,1987.5 756,1987.5 ccw(c756,1997.49) 763.07,1990.43 768.21,1995.57 cw(c775.28,1988.51) 775.28,1998.5 810.68,1998.5 ccw(c810.68,2098.5) 881.39,2027.79 951.31,2097.71 cw(c1022.02,2027) 1022.02,2127 1825.58,2127 cw(c1825.58,2027) 1896.29,2097.71 1958.26,2035.74 ccw(c2048.77,2126.25) 1958.32,2035.68 ccw(c2048.77,2126.25) 2048.77,1998.25 2110.67,1998.25 cw(c2110.67,1988.41) 2117.63,1995.37 2123.02,1989.98 ccw(c2130.21,1997.17) 2130.21,1987 2562.74,1987 cw(c2562.74,1936.89) 2563.74,1986.99 cw(c2562.74,1936.89) 2598.17,1972.33 ; 2598.18,1972.32 v1(2608,1962.5)
ADC_DB0_P: J1.B4 J2.B4 J4.B4 | length 2134.6
  L1_Top Layer w10: J1.B4@585,2012.5 596.53,2024.03 cw(c629.05,1991.51) 629.05,2037.5 756,2037.5 cw(c756,2027.51) 763.07,2034.57 768.21,2029.43 ccw(c775.28,2036.49) 775.28,2026.5 797,2026.5 ccw(c797,2131.52) 871.26,2057.26 931.51,2117.51 cw(c1022.02,2027) 1022.02,2155 1825.58,2155 cw(c1825.58,2027) 1916.09,2117.51 1969.86,2063.74 ; 1969.91,2063.68 cw(c2060.37,2154.25) 1969.86,2063.74 ; v1(2608,2012.5) 2592.9,2027.6 ccw(c2569,2003.7) 2569,2037.5 2129,2037.5 ccw(c2129,2027.51) 2121.93,2034.57 2116.79,2029.43 cw(c2109.72,2036.49) 2109.72,2026.5 2109.47,2026.25 2048.77,2026.25 cw(c2048.77,2126.25) 1978.06,2055.54 1969.86,2063.74
ADC_DB1_N: J1.B9 J2.B9 J4.B9 | length 2178
  L1_Top Layer w10: J1.B9@585,1762.5 596.53,1774.03 cw(c629.05,1741.51) 629.05,1787.5 749.72,1787.5 ccw(c749.72,1806.28) 763,1793 cw(c776.28,1779.72) 776.28,1798.5 813.68,1798.5 ccw(c813.68,1898.5) 884.39,1827.79 1008.31,1951.71 cw(c1079.02,1881) 1079.02,1981 1779.98,1981 cw(c1779.98,1881) 1850.69,1951.71 1966.66,1835.74 ccw(c2057.17,1926.25) 1966.72,1835.68 ccw(c2057.17,1926.25) 2057.17,1798.25 2110.67,1798.25 cw(c2110.67,1788.41) 2117.63,1795.37 2123.02,1789.98 ccw(c2130.21,1797.17) 2130.21,1787 2562.74,1787 ; 2563.74,1786.99 cw(c2562.74,1736.89) 2598.17,1772.33 ; 2598.18,1772.32 v1(2608,1762.5)
ADC_DB1_P: J1.B8 J2.B8 J4.B8 | length 2179.4
  L1_Top Layer w10: J1.B8@585,1812.5 596.53,1824.03 cw(c629.05,1791.51) 629.05,1837.5 757,1837.5 cw(c757,1827.51) 764.07,1834.57 769.21,1829.43 ccw(c776.28,1836.49) 776.28,1826.5 802,1826.5 ccw(c802,1926.69) 872.84,1855.84 988.51,1971.51 cw(c1079.02,1881) 1079.02,2009 1779.98,2009 cw(c1779.98,1881) 1870.49,1971.51 1986.46,1855.54 ccw(c2057.17,1926.25) 1986.71,1855.29 ccw(c2057.17,1926.25) 2057.17,1826.25 2109.11,1826.25 ccw(c2109.11,1837.11) 2109.47,1826.26 ccw(c2109.11,1837.11) 2116.79,1829.43 2121.93,1834.57 cw(c2129,1827.51) 2129,1837.5 2569,1837.5 cw(c2569,1803.7) 2592.9,1827.6 v1(2608,1812.5)
ADC_DB2_N: J1.Y11 J4.Y11 | length 2125.1
  L1_Top Layer w10: J1.Y11@743,1670.5 cw(c750.24,1663.26) 750.24,1673.5 868.08,1673.5 ccw(c868.08,1801.5) 958.59,1710.99 1044.31,1796.71 cw(c1115.02,1726) 1115.02,1826 1714.98,1826 cw(c1714.98,1726) 1785.69,1796.71 1846.91,1735.49 ccw(c1937.42,1826) 1846.97,1735.43 ccw(c1937.42,1826) 1926.12,1698.5 ccw(c1937.42,1826) 1937.42,1698 2110.92,1698 cw(c2110.92,1689.7) 2116.78,1695.58 ; 2116.79,1695.57 2121.93,1690.43 ccw(c2129,1697.49) 2129,1687.5 2721.4,1687.5 cw(c2721.4,1659.5) 2741.2,1679.3 v1(2758,1662.5)
ADC_DB2_P: J1.Y10 J4.Y10 | length 2124.6
  L1_Top Layer w10: J1.Y10@743,1704.5 ccw(c750.24,1711.74) 750.24,1701.5 868.08,1701.5 ccw(c868.08,1801.5) 938.79,1730.79 1024.51,1816.51 cw(c1115.02,1726) 1115.02,1854 1714.98,1854 cw(c1714.98,1726) 1805.49,1816.51 1866.71,1755.29 ccw(c1937.42,1826) 1927.43,1726.5 ccw(c1937.42,1826) 1937.42,1726 2108.51,1726 ccw(c2108.51,1737.71) 2116.75,1729.4 ; 2116.79,1729.43 2121.93,1734.57 cw(c2129,1727.51) 2129,1737.5 2713.95,1737.5 cw(c2713.95,1691.51) 2746.47,1724.03 v1(2758,1712.5)
ADC_DB3_N: J1.Y15 J4.Y15 | length 2096.1
  L1_Top Layer w10: J1.Y15@743,1470.5 cw(c750.24,1463.26) 750.24,1473.5 780.06,1473.5 ccw(c780.06,1533.94) 822.8,1491.2 cw(c839.21,1474.79) 839.21,1498 933,1498 cw(c933,1403.85) 999.58,1470.42 1032.51,1437.49 ccw(c1123.02,1528) 1123.02,1400 1641.58,1400 ccw(c1641.58,1528) 1732.09,1437.49 1763.31,1468.71 cw(c1834.02,1398) 1834.02,1498 2110.92,1498 cw(c2110.92,1489.7) 2116.78,1495.58 ; 2116.79,1495.57 2121.93,1490.43 ccw(c2129,1497.49) 2129,1487.5 2713.95,1487.5 cw(c2713.95,1441.51) 2746.47,1474.03 v1(2758,1462.5)
ADC_DB3_P: J1.Y14 J4.Y14 | length 2096.4
  L1_Top Layer w10: J1.Y14@743,1504.5 ccw(c750.24,1511.74) 750.24,1501.5 780.06,1501.5 ccw(c780.06,1533.94) 803,1511 cw(c839.21,1474.79) 839.21,1526 933,1526 cw(c933,1403.85) 1019.38,1490.22 1052.31,1457.29 ccw(c1123.02,1528) 1123.02,1428 1641.58,1428 ccw(c1641.58,1528) 1712.29,1457.29 1743.51,1488.51 cw(c1834.02,1398) 1834.02,1526 2108.51,1526 ccw(c2108.51,1527.71) 2109.72,1526.5 ccw(c2109.72,1536.49) 2116.79,1529.43 2121.93,1534.57 cw(c2129,1527.51) 2129,1537.5 2713.95,1537.5 cw(c2713.95,1491.51) 2746.47,1524.03 v1(2758,1512.5)
ADC_DB4_N: J1.Y19 J4.Y19 | length 2150.8
  L1_Top Layer w10: J1.Y19@743,1270.5 cw(c750.24,1263.26) 750.24,1273.5 775.34,1273.5 cw(c775.34,1210.34) 820,1255 923.51,1151.49 ccw(c1014.02,1242) 1014.02,1114 1781.98,1114 ccw(c1781.98,1242) 1872.49,1151.49 1981.51,1260.51 cw(c2072.02,1170) 1981.57,1260.57 cw(c2072.02,1170) 2072.02,1298 2110.92,1298 cw(c2110.92,1289.7) 2116.78,1295.58 ; 2116.79,1295.57 2121.93,1290.43 ccw(c2129,1297.49) 2129,1287.5 2713.95,1287.5 cw(c2713.95,1241.51) 2746.47,1274.03 v1(2758,1262.5)
ADC_DB4_P: J1.Y18 J4.Y18 | length 2153.5
  L1_Top Layer w10: J1.Y18@743,1304.5 ccw(c750.24,1311.74) 750.24,1301.5 775.34,1301.5 cw(c775.34,1210.34) 839.8,1274.8 943.31,1171.29 ccw(c1014.02,1242) 1014.02,1142 1781.98,1142 ccw(c1781.98,1242) 1852.69,1171.29 1978.11,1296.71 cw(c2048.82,1226) 2030.52,1324.31 cw(c2048.82,1226) 2048.82,1326 2108.51,1326 ccw(c2108.51,1327.71) 2109.72,1326.5 ccw(c2109.72,1336.49) 2116.79,1329.43 2121.93,1334.57 cw(c2129,1327.51) 2129,1337.5 2713.95,1337.5 cw(c2713.95,1291.51) 2746.47,1324.03 v1(2758,1312.5)
ADC_DB5_N: J1.Y23 J4.Y23 | length 2100.4
  L1_Top Layer w10: J1.Y23@735,1062.5 743,1070.5 cw(c750.24,1063.26) 750.24,1073.5 806.48,1073.5 cw(c806.48,973.5) 877.19,1044.21 904.11,1017.29 ccw(c974.82,1088) 974.82,988 1845.98,988 ccw(c1845.98,1116) 1936.43,1025.43 ccw(c1845.98,1116) 1936.49,1025.49 1971.51,1060.51 cw(c2062.02,970) 1971.57,1060.57 cw(c2062.02,970) 2062.02,1098 2110.92,1098 cw(c2110.92,1089.7) 2116.78,1095.58 ; 2116.79,1095.57 2121.93,1090.43 ccw(c2129,1097.49) 2129,1087.5 2713.95,1087.5 cw(c2713.95,1041.51) 2746.47,1074.03 v1(2758,1062.5)
ADC_DB5_P: J1.Y22 J4.Y22 | length 2100.7
  L1_Top Layer w10: J1.Y22@735,1112.5 743,1104.5 ccw(c750.24,1111.74) 750.24,1101.5 806.48,1101.5 cw(c806.48,973.5) 896.99,1064.01 907.51,1053.49 ccw(c998.02,1144) 998.02,1016 1845.98,1016 ccw(c1845.98,1116) 1916.69,1045.29 1968.11,1096.71 cw(c2038.82,1026) 2038.82,1126 2108.51,1126 ccw(c2108.51,1127.71) 2109.72,1126.5 ccw(c2109.72,1136.49) 2116.79,1129.43 2121.93,1134.57 cw(c2129,1127.51) 2129,1137.5 2713.95,1137.5 cw(c2713.95,1091.51) 2746.47,1124.03 v1(2758,1112.5)
ADC_DB6_N: J1.Z13 J4.Z13 | length 2101.6
  L1_Top Layer w10: J1.Z13@685.52,1562.5 J1.Z13@685,1562.5 696.53,1574.03 cw(c729.05,1541.51) 729.05,1587.5 754,1587.5 ccw(c754,1597.49) 761.07,1590.43 766.21,1595.57 cw(c773.28,1588.51) 773.28,1598.5 1007.74,1598.5 ccw(c1007.74,1724.9) 1097.12,1635.52 ; 1097.53,1635.93 ccw(c1007.08,1726.5) 1097.59,1635.99 1119.31,1657.71 cw(c1190.02,1587) 1190.02,1687 1640.97,1687 cw(c1640.97,1587) 1711.68,1657.71 1733.9,1635.49 ccw(c1824.41,1726) 1761.54,1614.5 ccw(c1824.41,1726) 1824.41,1598 2105,1598 cw(c2105,1585.93) 2113.54,1594.46 2115.34,1592.66 ccw(c2129,1606.31) 2129,1587 2669.18,1587 cw(c2669.18,1556.18) 2690.98,1577.97 v1@2707.23,1561.73 ; v1@2707.06,1562.89 ccw(c2708,1563.83) v1(2708,1562.5)
ADC_DB6_P: J1.Z12 J4.Z12 | length 2102.2
  L1_Top Layer w10: J1.Z12@685,1612.5 696.53,1624.03 cw(c729.05,1591.51) 729.05,1637.5 754,1637.5 cw(c754,1627.51) 761.07,1634.57 766.21,1629.43 ccw(c773.28,1636.49) 773.28,1626.5 1007.74,1626.5 ccw(c1007.74,1724.9) 1077.32,1655.32 ccw(c1006.83,1726.25) 1077.54,1655.54 1099.51,1677.51 cw(c1190.02,1587) 1190.02,1715 1640.97,1715 cw(c1640.97,1587) 1731.48,1677.51 1753.7,1655.29 ccw(c1824.41,1726) 1824.41,1626 2108.51,1626 ; 2109.21,1626 2108.51,1626 ; 2109.21,1626.26 ccw(c2109.21,1637.97) 2109.43,1626.27 ; 2117.27,1629.91 2121.93,1634.57 cw(c2129,1627.51) 2129,1637.5 2663.95,1637.5 cw(c2663.95,1591.51) 2696.47,1624.03 v1(2708,1612.5) ; 2117.49,1629.7 cw(c2109.21,1637.97) 2109.43,1626.27 ; 2108.51,1626 ccw(c2108.51,1627.71) 2109.43,1626.27
ADC_DB7_N: J1.Z17 J4.Z17 | length 2159.7
  L1_Top Layer w10: J1.Z17@685,1362.5 696.53,1374.03 cw(c729.05,1341.51) 729.05,1387.5 754,1387.5 ccw(c754,1397.49) 761.07,1390.43 766.21,1395.57 cw(c773.28,1388.51) 773.28,1398.5 817.08,1398.5 cw(c817.08,1298.5) 887.79,1369.21 975.71,1281.29 ccw(c1046.42,1352) 1046.42,1252 1711.58,1252 ccw(c1711.58,1380) 1802.09,1289.49 1881.56,1368.96 cw(c1952.27,1298.25) 1945.2,1398 ; 1935,1398 1945.2,1398 ; v1@2707.23,1361.73 2690.98,1377.97 ccw(c2669.18,1356.18) 2669.18,1387 2129,1387 cw(c2129,1406.31) 2115.34,1392.66 2113.54,1394.46 ccw(c2105,1385.93) 2105,1398 1945.2,1398
  other v1: 2708,1362.5
ADC_DB7_P: J1.Z16 J4.Z16 | length 2158
  L1_Top Layer w10: J1.Z16@685,1412.5 696.53,1424.03 cw(c729.05,1391.51) 729.05,1437.5 754,1437.5 cw(c754,1427.51) 761.07,1434.57 766.21,1429.43 ccw(c773.28,1436.49) 773.28,1426.5 817.08,1426.5 cw(c817.08,1298.5) 907.59,1389.01 979.11,1317.49 ccw(c1069.62,1408) 1069.62,1280 1711.58,1280 ccw(c1711.58,1380) 1782.29,1309.29 1861.76,1388.76 cw(c1952.27,1298.25) 1861.82,1388.82 cw(c1952.27,1298.25) 1944.27,1426 ; 1935,1426 1944.27,1426 ; 2109.21,1426 2108.51,1426 ; 2109.21,1426.26 ccw(c2109.21,1437.97) 2109.43,1426.27 ; 2117.27,1429.91 2121.93,1434.57 cw(c2129,1427.51) 2129,1437.5 2663.95,1437.5 cw(c2663.95,1391.51) 2696.47,1424.03 v1(2708,1412.5) ; 2117.49,1429.7 cw(c2109.21,1437.97) 2109.43,1426.27 ; 1944.27,1426 2108.51,1426 ; 2108.51,1426 ccw(c2108.51,1427.71) 2109.43,1426.27
ADC_SYNC_N: J2.G13 J4.G13 R48.2 | length 970.1
  L1_Top Layer w6: R48.2@1445.62,1529 1465.62,1549 1510,1549 1519.51,1539.49 v1(1519.51,1537.5)
  L4_Signal layer1 w4.9: v1(1519.51,1537.5) 1529.51,1547.5 1873.5,1547.5 1895,1526 2080.97,1526 2135.97,1581 2339.5,1581 v1(2358,1562.5)
ADC_SYNC_P: J2.G12 J4.G12 R47.2 | length 968.5
  L1_Top Layer w6: R47.2@1445.62,1580 1465.62,1560 1510,1560 v1(1519.5,1569.5)
  L4_Signal layer1 w4.9: v1(1519.5,1569.5) 1529.5,1559.5 1878.47,1559.5 1899.97,1538 2076,1538 2131,1593 2338.5,1593 v1(2358,1612.5)
C18: J1.C18 J2.C18 J4.C18 | length 2073.1
  L8_Signal Layer3 w4.25: v1(535,1312.5) 555.5,1292 2156,1292 2196,1332 2433,1332 2473,1292 2537.5,1292 v1(2558,1312.5)
C34: J1.C34 J2.C34 J4.C34 | length 2110.4
  L8_Signal Layer3 w4.25: v1(535,512.5) 554.5,493 835,493 902.5,425.5 1934.34,425.5 2039.84,531 2539.5,531 v1(2558,512.5)
C35: J1.C35 J2.C35 J4.C35 | length 2085.1
  L8_Signal Layer3 w4.25: v1(535,462.5) 567.88,429.62 852.62,429.62 875.25,407 1981,407 2056,482 2538.5,482 v1(2558,462.5)
C37: J1.C37 J2.C37 J4.C37 | length 2083.1
  L8_Signal Layer3 w4.25: v1(535,362.5) 535,362.12 560,337.12 781.13,337.12 828,290.25 2372.25,290.25 2420,338 2533.5,338 v1(2558,362.5)
C39: J1.C39 J2.C39 J4.C39 | length 2049.1
  L8_Signal Layer3 w4.25: v1(535,262.5) 566.5,231 1250.6,231 1263.6,244 2539.5,244 v1(2558,262.5)
D1: J1.D1 J2.D1 J4.D1 | length 2045
  L8_Signal Layer3 w4.25: v1(485,2162.5) 511.5,2136 2481.5,2136 v1(2508,2162.5)
D17: J1.D17 J2.D17 J4.D17 | length 2039.8
  L10_Signal Layer4 w6.5: v1(485,1362.5) 505.25,1382.75 2487.75,1382.75 v1(2508,1362.5)
D18: J1.D18 J2.D18 J4.D18 | length 2047.4
  L8_Signal Layer3 w4.25: v1(485,1312.5) 502.5,1330 1979,1330 1991,1342 2478.5,1342 v1(2508,1312.5)
D32: J1.D32 J2.D32 J4.D32 | length 2191.3
  L8_Signal Layer3 w4.25: v1(485,612.5) 505.25,592.25 948.25,592.25 955,599 1398,599 1437,560 1437,488 1458,467 1919,467 2039,587 2482.5,587 v1(2508,612.5)
D35: J1.D35 J2.D35 J4.D35 | length 2205.7
  L6_Signal Layer2 w3.75: v1(485,462.5) 504,443.5 736.5,443.5 938,242 1935.6,242 2081.6,388 2433.5,388 v1(2508,462.5)
D36: J1.D36 J2.D36 J4.D36 | length 2110.8
  L8_Signal Layer3 w4.25: v1(485,412.5) 515.5,382 788,382 839,331 1974,331 2080,437 2483.5,437 v1(2508,412.5)
D38: J1.D38 J2.D38 J4.D38 | length 2049.1
  L8_Signal Layer3 w4.25: v1(485,312.5) 516.5,281 2476.5,281 v1(2508,312.5)
D40: J1.D40 J2.D40 J4.D40 | length 2047.6
  L8_Signal Layer3 w4.25: v1(485,212.5) 514.75,182.75 2478.25,182.75 v1(2508,212.5)
DAC_ALT_SYNC_N: J1.F20 J2.F20 J4.F20 | length 2091.3
  L4_Signal layer1 w4.9: v1(385,1212.5) 404,1231.5 735.47,1231.5 798.97,1295 2111,1295 2174,1232 2388.5,1232 v1(2408,1212.5)
DAC_ALT_SYNC_P: J1.F19 J2.F19 J4.F19 | length 2090.9
  L4_Signal layer1 w4.9: v1(385,1262.5) 404,1243.5 730.5,1243.5 794,1307 2115.97,1307 2178.97,1244 2389.5,1244 v1(2408,1262.5)
DAC_DA0_N: J1.C3 J2.C3 J4.C3 | length 2096.8
  L4_Signal layer1 w5.5: v1(535,2062.5) cw(c602.36,1995.14) 602.36,2090.4 769.44,2090.4 ccw(c769.44,2104.06) 779.1,2094.4 cw(c792.38,2081.12) 792.38,2099.9 865.46,2099.9 ccw(c865.46,2226.5) 954.98,2136.98 974,2156 cw(c1053.67,2076.33) 1053.67,2189 1752.58,2189 cw(c1752.58,2089) 1823.29,2159.71 1846.02,2136.98 ccw(c1935.54,2226.5) 1935.54,2099.9 2054.12,2099.9 cw(c2054.12,2081.12) 2067.4,2094.4 ccw(c2077.06,2104.06) 2077.06,2090.4 2490.64,2090.4 cw(c2490.64,1995.14) v1(2558,2062.5)
DAC_DA0_P: J1.C2 J2.C2 J4.C2 | length 2096.1
  L4_Signal layer1 w5.5: v1(535,2112.5) cw(c591.73,2055.77) 591.73,2136 769.46,2136 cw(c769.46,2122.34) 779.11,2132 ccw(c792.39,2145.28) 792.39,2126.5 865.46,2126.5 ccw(c865.46,2226.5) 878.98,2127.42 ccw(c865.46,2226.5) 936.17,2155.79 966.69,2186.31 cw(c1037.4,2115.6) 1037.4,2215.6 1752.58,2215.6 cw(c1752.58,2089) 1842.1,2178.52 1864.83,2155.79 ccw(c1935.54,2226.5) 1935.54,2126.5 2054.11,2126.5 ccw(c2054.11,2145.28) 2067.39,2132 cw(c2077.04,2122.34) 2077.04,2136 2501.27,2136 cw(c2501.27,2055.77) v1(2558,2112.5)
DAC_DA1_N: J1.A23 J2.A23 J4.A23 | length 2092.4
  L4_Signal layer1 w5.5: v1(635,1062.5) cw(c702.36,995.14) 702.36,1090.4 769.44,1090.4 ccw(c769.44,1104.06) 779.1,1094.4 cw(c792.38,1081.12) 792.38,1099.9 860.34,1099.9 ccw(c860.34,1189.66) 923.81,1126.19 946.33,1148.71 cw(c1017.04,1078) 1017.04,1178 1819.96,1178 cw(c1819.96,1078) 1890.67,1148.71 1920.19,1119.19 ccw(c1966.76,1165.76) 1966.76,1099.9 2054.12,1099.9 cw(c2054.12,1081.12) 2067.4,1094.4 ccw(c2077.06,1104.06) 2077.06,1090.4 2590.64,1090.4 cw(c2590.64,995.14) v1(2658,1062.5)
DAC_DA1_P: J1.A22 J2.A22 J4.A22 | length 2090
  L4_Signal layer1 w5.5: v1(635,1112.5) cw(c691.73,1055.77) 691.73,1136 769.46,1136 cw(c769.46,1122.34) 779.11,1132 ccw(c792.39,1145.28) 792.39,1126.5 860.34,1126.5 ccw(c860.34,1189.66) 905,1145 927.52,1167.52 cw(c1017.04,1078) 1017.04,1204.6 1819.96,1204.6 cw(c1819.96,1078) 1909.48,1167.52 1939,1138 ccw(c1966.76,1165.76) 1966.76,1126.5 2054.11,1126.5 ccw(c2054.11,1145.28) 2067.39,1132 cw(c2077.04,1122.34) 2077.04,1136 2601.27,1136 cw(c2601.27,1055.77) v1(2658,1112.5)
DAC_DA2_N: J1.A27 J2.A27 J4.A27 | length 2121.8
  L4_Signal layer1 w5.5: v1(635,862.5) cw(c702.36,795.14) 702.36,890.4 769.44,890.4 ccw(c769.44,904.06) 779.1,894.4 cw(c792.38,881.12) 792.38,899.9 883.08,899.9 ccw(c883.08,1026.5) 972.6,936.98 1024.33,988.71 cw(c1095.04,918) 1095.04,1018 1752.58,1018 cw(c1752.58,918) 1823.29,988.71 1878,934 ccw(c1960.33,1016.33) 1960.33,899.9 2054.12,899.9 cw(c2054.12,881.12) 2067.4,894.4 ccw(c2077.06,904.06) 2077.06,890.4 2590.64,890.4 cw(c2590.64,795.14) v1(2658,862.5)
DAC_DA2_P: J1.A26 J2.A26 J4.A26 | length 2119.4
  L4_Signal layer1 w5.5: v1(635,912.5) cw(c691.73,855.77) 691.73,936 769.46,936 cw(c769.46,922.34) 779.11,932 ccw(c792.39,945.28) 792.39,926.5 883.08,926.5 ccw(c883.08,1026.5) 953.79,955.79 1005.52,1007.52 cw(c1095.04,918) 1095.04,1044.6 1752.58,1044.6 cw(c1752.58,918) 1842.1,1007.52 1896.81,952.81 ccw(c1960.32,1016.33) 1960.32,926.5 2054.11,926.5 ccw(c2054.11,945.28) 2067.39,932 cw(c2077.04,922.34) 2077.04,936 2601.27,936 cw(c2601.27,855.77) v1(2658,912.5)
DAC_DA3_N: J1.A31 J2.A31 J4.A31 | length 2082
  L4_Signal layer1 w5.5: v1(635,662.5) cw(c702.36,595.14) 702.36,690.4 769.44,690.4 ccw(c769.44,704.06) 779.1,694.4 cw(c792.38,681.12) 792.38,699.9 826.92,699.9 ccw(c826.92,793.08) 892.81,727.19 903.33,737.71 cw(c974.04,667) 974.04,767 1843.13,767 cw(c1843.13,702.13) 1889,748 1900.02,736.98 ccw(c1989.54,826.5) 1989.54,699.9 2054.12,699.9 cw(c2054.12,681.12) 2067.4,694.4 ccw(c2077.06,704.06) 2077.06,690.4 2590.64,690.4 cw(c2590.64,595.14) v1(2658,662.5)
DAC_DA3_P: J1.A30 J2.A30 J4.A30 | length 2079.7
  L4_Signal layer1 w5.5: v1(635,712.5) cw(c691.73,655.77) 691.73,736 769.46,736 cw(c769.46,722.34) 779.11,732 ccw(c792.39,745.28) 792.39,726.5 826.92,726.5 ccw(c826.92,793.08) 874,746 884.52,756.52 cw(c974.04,667) 974.04,793.6 1843.13,793.6 cw(c1843.13,702.13) 1907.81,766.81 1918.83,755.79 ccw(c1989.54,826.5) 1989.54,726.5 2054.11,726.5 ccw(c2054.11,745.28) 2067.39,732 cw(c2077.04,722.34) 2077.04,736 2601.27,736 cw(c2601.27,655.77) v1(2658,712.5)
